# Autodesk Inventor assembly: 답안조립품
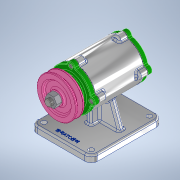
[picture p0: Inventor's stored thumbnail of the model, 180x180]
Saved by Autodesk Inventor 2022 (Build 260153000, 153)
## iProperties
Created: 2023-05
Part Number: 답안조립품
Document SubType Name: Assembly
Designer: Admin
Author: Admin
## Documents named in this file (12)
- C:\Users\Admin\Desktop\730508V1003\답안조립품.iam
- C:\Users\Admin\Desktop\730508V1003\본체.ipt
- C:\Users\Admin\Desktop\730508V1003\개스킷.ipt
- C:\Users\Admin\Desktop\730508V1003\뒤커버.ipt
- C:\Users\Admin\Desktop\730508V1003\앞커버.ipt
- C:\Users\Admin\Desktop\730508V1003\베어링 6204.ipt
- C:\Users\Admin\Desktop\730508V1003\오일 실.ipt
- C:\Users\Admin\Desktop\730508V1003\축.ipt
- C:\Users\Admin\Desktop\730508V1003\볼트 M4 x 12.ipt
- C:\Users\Admin\Desktop\730508V1003\키 4 x 4.ipt
- C:\Users\Admin\Desktop\730508V1003\V-벨트풀리.ipt
- C:\Users\Admin\Desktop\730508V1003\너트 M12 x 1.25.ipt
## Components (8 placed, 6 different names)
1. 개스킷:1
2. 개스킷:2
3. KS B 2023 6204 - 20 x 47 x 14:1
4. KS B 2023 6204 - 20 x 47 x 14:2
5. KS B 2804 D D - 20 32 8:1
6. KS B 1311 (I) 4 x 4 x 12:1
7. V-벨트풀리:1
8. KS B 1012 클래스 1 일반 - 미터 M12x1.25:1
